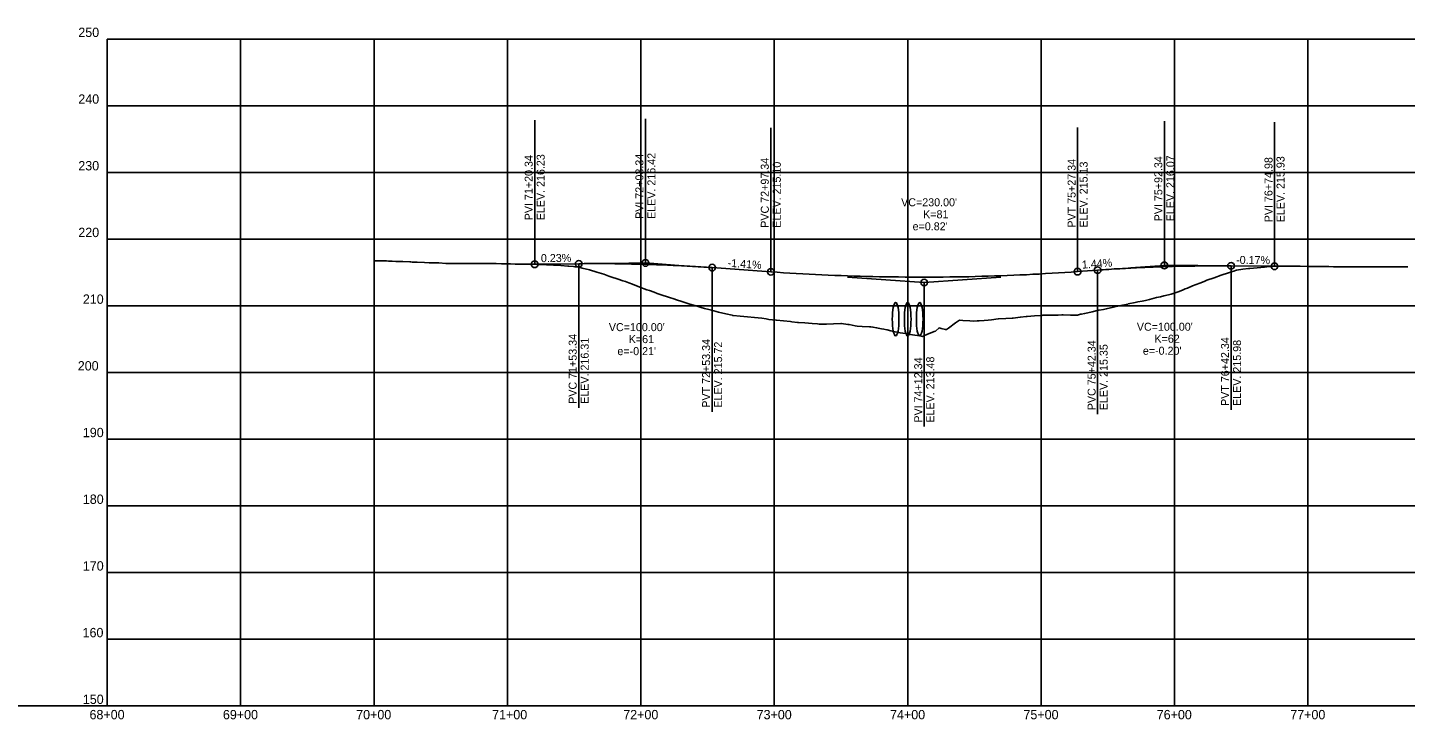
# Model space of a CAD drawing. Extents: x 1138442 to 1165793, y 1654070 to 1657687.
# Drawn here: x 1163494 to 1164527, y 1654070 to 1654589 of the extents above; entities that cross this region are included whole.
import ezdxf

# ---------------------------------------------------------------- set-up
doc = ezdxf.new("R2010")
doc.units = 0
for name, color, linetype in [('B_Dimensions', 7, 'Continuous'), ('R_Axis', 7, 'Continuous'), ('R_Axis Annot', 7, 'Continuous'), ('R_Concrete', 7, 'Continuous'), ('R_Grid', 7, 'Continuous'), ('R_No Plot', 7, 'Continuous'), ('R_Proposed Const Limits_Hand', 7, 'Continuous'), ('R_Vert Alg Annot', 7, 'Continuous')]:
    doc.layers.add(name, color=color, linetype=linetype)

msp = doc.modelspace()

# ---------------------------------------------------------------- linework, layer by layer
at = {"layer": 'B_Dimensions'}
for p, q in [((1163874, 1654411.5), (1163907, 1654411.9)), ((1163932, 1654412.2), (1163957, 1654412.5)), ((1163957, 1654412.5), (1163982, 1654410.7)), ((1164007, 1654409), (1164051, 1654405.9)), ((1164281, 1654406), (1164296, 1654407.1)), ((1164321, 1654408.9), (1164346, 1654410.7)), ((1164346, 1654410.7), (1164371, 1654410.5)), ((1164396, 1654410.3), (1164428.6, 1654410)), ((1164108.5, 1654401.8), (1164166, 1654397.8)), ((1164166, 1654397.8), (1164223.5, 1654401.9))]:
    msp.add_line(p, q, dxfattribs=at)
for points in [[(1163907, 1654411.9), (1163909.1, 1654411.9), (1163911.1, 1654412), (1163913.2, 1654412), (1163915.3, 1654412), (1163917.4, 1654412), (1163919.5, 1654412), (1163921.6, 1654412), (1163923.6, 1654412), (1163925.7, 1654412), (1163927.8, 1654412), (1163929.9, 1654412), (1163932, 1654412), (1163934.1, 1654411.9), (1163936.1, 1654411.9), (1163938.2, 1654411.9), (1163940.3, 1654411.9), (1163942.4, 1654411.8), (1163944.5, 1654411.8), (1163946.6, 1654411.7), (1163948.6, 1654411.7), (1163950.7, 1654411.6), (1163952.8, 1654411.6), (1163954.9, 1654411.5), (1163959.1, 1654411.4), (1163961.1, 1654411.3), (1163963.2, 1654411.3), (1163965.3, 1654411.2), (1163967.4, 1654411.1), (1163969.5, 1654411), (1163971.6, 1654411), (1163973.6, 1654410.9), (1163975.7, 1654410.8), (1163977.8, 1654410.7), (1163979.9, 1654410.6), (1163982, 1654410.5), (1163984.1, 1654410.4), (1163986.1, 1654410.3), (1163988.2, 1654410.2), (1163990.3, 1654410), (1163992.4, 1654409.9), (1163994.5, 1654409.8), (1163996.6, 1654409.7), (1163998.6, 1654409.5), (1164000.7, 1654409.4), (1164002.8, 1654409.3), (1164004.9, 1654409.1), (1164007, 1654409)], [(1164051, 1654405.9), (1164055.8, 1654405.5), (1164060.6, 1654405.2), (1164065.3, 1654404.9), (1164070.1, 1654404.6), (1164074.9, 1654404.4), (1164079.7, 1654404.1), (1164084.5, 1654403.9), (1164089.3, 1654403.6), (1164094.1, 1654403.4), (1164098.9, 1654403.2), (1164103.7, 1654403), (1164108.5, 1654402.8), (1164113.3, 1654402.7), (1164118.1, 1654402.5), (1164122.8, 1654402.4), (1164127.6, 1654402.3), (1164132.4, 1654402.2), (1164137.2, 1654402.1), (1164142, 1654402), (1164146.8, 1654402), (1164151.6, 1654401.9), (1164156.4, 1654401.9), (1164161.2, 1654401.9), (1164170.8, 1654401.9), (1164175.6, 1654401.9), (1164180.3, 1654401.9), (1164185.1, 1654402), (1164189.9, 1654402.1), (1164194.7, 1654402.1), (1164199.5, 1654402.2), (1164204.3, 1654402.3), (1164209.1, 1654402.5), (1164213.9, 1654402.6), (1164218.7, 1654402.8), (1164223.5, 1654402.9), (1164228.3, 1654403.1), (1164233.1, 1654403.3), (1164237.8, 1654403.5), (1164242.6, 1654403.7), (1164247.4, 1654404), (1164252.2, 1654404.2), (1164257, 1654404.5), (1164261.8, 1654404.8), (1164266.6, 1654405.1), (1164271.4, 1654405.4), (1164276.2, 1654405.7), (1164281, 1654406)], [(1164296, 1654407.1), (1164298.1, 1654407.3), (1164300.1, 1654407.4), (1164302.2, 1654407.6), (1164304.3, 1654407.7), (1164306.4, 1654407.8), (1164308.5, 1654408), (1164310.6, 1654408.1), (1164312.6, 1654408.2), (1164314.7, 1654408.3), (1164316.8, 1654408.4), (1164318.9, 1654408.6), (1164321, 1654408.7), (1164323.1, 1654408.8), (1164325.1, 1654408.9), (1164327.2, 1654409), (1164329.3, 1654409.1), (1164331.4, 1654409.2), (1164333.5, 1654409.3), (1164335.6, 1654409.3), (1164337.6, 1654409.4), (1164339.7, 1654409.5), (1164341.8, 1654409.6), (1164343.9, 1654409.7), (1164348.1, 1654409.8), (1164350.1, 1654409.8), (1164352.2, 1654409.9), (1164354.3, 1654410), (1164356.4, 1654410), (1164358.5, 1654410.1), (1164360.6, 1654410.1), (1164362.6, 1654410.1), (1164364.7, 1654410.2), (1164366.8, 1654410.2), (1164368.9, 1654410.2), (1164371, 1654410.3), (1164373.1, 1654410.3), (1164375.1, 1654410.3), (1164377.2, 1654410.3), (1164379.3, 1654410.3), (1164381.4, 1654410.3), (1164383.5, 1654410.3), (1164385.6, 1654410.3), (1164387.6, 1654410.3), (1164389.7, 1654410.3), (1164391.8, 1654410.3), (1164393.9, 1654410.3), (1164396, 1654410.3)]]:
    msp.add_lwpolyline(points, dxfattribs=at)
at = {"layer": 'R_Axis'}
for q in [(1163553.6, 1654580.4), (1165053.6, 1654080.4)]:
    msp.add_line((1163553.6, 1654080.4), q, dxfattribs=at)
at = {"layer": 'R_Concrete'}
for centre in [(1164144.6, 1654370.3), (1164153.6, 1654370.3), (1164162.6, 1654370.3)]:
    msp.add_ellipse(centre, major_axis=(0, -12.5), ratio=0.2, dxfattribs=at)
at = {"layer": 'R_Grid'}
for p, q in [((1163553.6, 1654580.4), (1165053.6, 1654580.4)), ((1163553.6, 1654580.4), (1165053.6, 1654580.4)), ((1163653.6, 1654080.4), (1163653.6, 1654580.4)), ((1163753.6, 1654080.4), (1163753.6, 1654580.4)), ((1163853.6, 1654080.4), (1163853.6, 1654580.4)), ((1163953.6, 1654080.4), (1163953.6, 1654580.4)), ((1164053.6, 1654080.4), (1164053.6, 1654580.4)), ((1164153.6, 1654080.4), (1164153.6, 1654580.4)), ((1164253.6, 1654080.4), (1164253.6, 1654580.4)), ((1164353.6, 1654080.4), (1164353.6, 1654580.4)), ((1164453.6, 1654080.4), (1164453.6, 1654580.4)), ((1163553.6, 1654530.4), (1165053.6, 1654530.4)), ((1163553.6, 1654480.4), (1165053.6, 1654480.4)), ((1163553.6, 1654430.4), (1165053.6, 1654430.4)), ((1163553.6, 1654380.4), (1165053.6, 1654380.4)), ((1163553.6, 1654330.4), (1165053.6, 1654330.4)), ((1163553.6, 1654280.4), (1165053.6, 1654280.4)), ((1163553.6, 1654230.4), (1165053.6, 1654230.4)), ((1163553.6, 1654180.4), (1165053.6, 1654180.4)), ((1163553.6, 1654130.4), (1165053.6, 1654130.4))]:
    msp.add_line(p, q, dxfattribs=at)
at = {"layer": 'R_No Plot'}
msp.add_line((1163553.6, 1654080.4), (1161984.5, 1654080.4), dxfattribs=at)
at = {"layer": 'R_Proposed Const Limits_Hand'}
msp.add_lwpolyline([(1163753.6, 1654414.2), (1163759, 1654414.1), (1163762.9, 1654414), (1163764.4, 1654413.9), (1163767, 1654413.8), (1163767.2, 1654413.8), (1163769.8, 1654413.7), (1163775.2, 1654413.5), (1163780.3, 1654413.3), (1163780.5, 1654413.3), (1163781.1, 1654413.3), (1163782.1, 1654413.2), (1163785.9, 1654413.1), (1163791.3, 1654412.9), (1163795, 1654412.7), (1163796.7, 1654412.7), (1163797.2, 1654412.7), (1163802.1, 1654412.5), (1163807.4, 1654412.2), (1163808.8, 1654412.2), (1163812.6, 1654412.2), (1163812.8, 1654412.2), (1163818.2, 1654412.2), (1163822.2, 1654412.2), (1163823.6, 1654412.1), (1163827.6, 1654412.1), (1163829, 1654412.1), (1163834.4, 1654412.1), (1163835.6, 1654412.1), (1163839.7, 1654412), (1163843.1, 1654412), (1163845.1, 1654412), (1163849.1, 1654411.9), (1163850.5, 1654411.9), (1163855.9, 1654411.8), (1163859.4, 1654411.7), (1163861.3, 1654411.7), (1163862.7, 1654411.7), (1163866.6, 1654411.6), (1163872, 1654411.6), (1163875, 1654411.5), (1163876, 1654411.5), (1163876.7, 1654411.4), (1163877.4, 1654411.4), (1163882.8, 1654411.1), (1163888.2, 1654410.8), (1163888.2, 1654410.8), (1163893.5, 1654410.5), (1163898.9, 1654410.1), (1163899.6, 1654410), (1163903, 1654409.8), (1163904.2, 1654409.7), (1163904.3, 1654409.7), (1163906.7, 1654409.5), (1163909.7, 1654408.7), (1163915.1, 1654407.3), (1163920.5, 1654405.7), (1163920.5, 1654405.7), (1163925.8, 1654404), (1163929.5, 1654402.7), (1163931.2, 1654402.2), (1163936.6, 1654400.4), (1163940.2, 1654399.2), (1163942, 1654398.6), (1163944.6, 1654397.7), (1163947.4, 1654396.6), (1163952.7, 1654394.4), (1163952.7, 1654394.4), (1163958.1, 1654392.4), (1163960, 1654391.8), (1163963.5, 1654390.5), (1163965.8, 1654389.7), (1163968.9, 1654388.6), (1163974.3, 1654386.8), (1163979.1, 1654385.3), (1163979.6, 1654385.1), (1163985, 1654383.4), (1163985.9, 1654383.2), (1163990.4, 1654381.7), (1163995.8, 1654380), (1163998.7, 1654379.1), (1164001.2, 1654378.4), (1164004.5, 1654377.6), (1164006.6, 1654377), (1164011.9, 1654375.7), (1164017.3, 1654374.4), (1164022.1, 1654373.3), (1164022.2, 1654373.2), (1164022.7, 1654373.1), (1164022.7, 1654373.1), (1164028.1, 1654372.6), (1164033.5, 1654372.2), (1164038.7, 1654371.7), (1164038.8, 1654371.7), (1164044.2, 1654371), (1164047.6, 1654370.5), (1164049.6, 1654370.2), (1164055, 1654369.5), (1164055.3, 1654369.5), (1164060.4, 1654369), (1164065.8, 1654368.5), (1164066.7, 1654368.4), (1164071.1, 1654367.9), (1164071.7, 1654367.9), (1164076.5, 1654367.5), (1164081.9, 1654367.1), (1164086, 1654366.8), (1164087.3, 1654366.7), (1164088.9, 1654366.5), (1164092.7, 1654366.6), (1164098, 1654366.8), (1164103.4, 1654367), (1164104.1, 1654367), (1164108.8, 1654366.4), (1164109.8, 1654366.3), (1164114.2, 1654365.4), (1164115.8, 1654365.1), (1164119.6, 1654364.9), (1164124.9, 1654364.7), (1164126, 1654364.6), (1164127.5, 1654364.4), (1164127.5, 1654364.4), (1164130.3, 1654363.9), (1164134, 1654363.2), (1164135.7, 1654362.9), (1164138.1, 1654362.4), (1164138.3, 1654362.4), (1164141.1, 1654361.7), (1164146.5, 1654360.5), (1164148.1, 1654360.1), (1164151.9, 1654359.6), (1164154.2, 1654359.2), (1164157.2, 1654358.7), (1164162.6, 1654357.8), (1164164.7, 1654357.4), (1164166.3, 1654358.1), (1164168, 1654358.8), (1164173.4, 1654361.1), (1164174.4, 1654361.5), (1164177.2, 1654363.9), (1164178.8, 1654363.4), (1164181.9, 1654362.6), (1164182.8, 1654362.6), (1164184.1, 1654363.6), (1164189.5, 1654367.5), (1164192.4, 1654369.6), (1164194.9, 1654369.4), (1164200.3, 1654369.1), (1164203.1, 1654368.9), (1164205.7, 1654369), (1164207.3, 1654369.1), (1164211, 1654369.3), (1164213.9, 1654369.5), (1164216.4, 1654369.8), (1164221.4, 1654370.5), (1164221.8, 1654370.6), (1164227.2, 1654370.8), (1164231.9, 1654371.1), (1164232.6, 1654371.2), (1164238, 1654371.8), (1164238.1, 1654371.8), (1164242.5, 1654372.4), (1164243.3, 1654372.4), (1164248.7, 1654372.8), (1164254.1, 1654373.2), (1164254.9, 1654373.3), (1164259.5, 1654373.3), (1164264.9, 1654373.3), (1164266.4, 1654373.3), (1164269.2, 1654373.5), (1164270.2, 1654373.5), (1164275.6, 1654373.4), (1164280.5, 1654373.3), (1164281, 1654373.4), (1164283.1, 1654374), (1164283.7, 1654374), (1164286.4, 1654374.7), (1164291.8, 1654375.9), (1164296.6, 1654377.1), (1164297.2, 1654377.2), (1164300.3, 1654377.6), (1164302.5, 1654378.1), (1164307.9, 1654379.4), (1164310, 1654379.9), (1164313.3, 1654380.6), (1164318.7, 1654381.7), (1164318.9, 1654381.8), (1164324.1, 1654382.8), (1164326.2, 1654383.3), (1164329.4, 1654383.9), (1164331.8, 1654384.4), (1164334.8, 1654385.2), (1164340.2, 1654386.5), (1164343.1, 1654387.2), (1164345.6, 1654387.8), (1164345.8, 1654387.9), (1164351, 1654389.2), (1164355.7, 1654390.5), (1164356.3, 1654390.8), (1164359.5, 1654392.2), (1164361.7, 1654393.1), (1164363.3, 1654393.7), (1164367.1, 1654395.3), (1164372.5, 1654397.4), (1164375.8, 1654398.7), (1164377.9, 1654399.5), (1164383.3, 1654401.4), (1164388.6, 1654403.3), (1164394, 1654405.1), (1164395.7, 1654405.7), (1164397.2, 1654406.2), (1164398, 1654406.4), (1164399.4, 1654406.9), (1164400.1, 1654407.2), (1164404.8, 1654407.8), (1164409, 1654408.3), (1164410.2, 1654408.4), (1164415.5, 1654408.9), (1164418.4, 1654409.1), (1164419.8, 1654409.3), (1164420.9, 1654409.4), (1164421.2, 1654409.4), (1164422.9, 1654409.5), (1164426.3, 1654409.8), (1164428.6, 1654410), (1164431.7, 1654410), (1164437.1, 1654410), (1164439.2, 1654410), (1164442.5, 1654410), (1164447.8, 1654410), (1164453.2, 1654409.9), (1164454.2, 1654409.9), (1164458.6, 1654409.9), (1164463.1, 1654409.8), (1164464, 1654409.8), (1164469.4, 1654409.8), (1164472.7, 1654409.7), (1164474.7, 1654409.7), (1164480.1, 1654409.7), (1164485.5, 1654409.6), (1164486.9, 1654409.6), (1164490.9, 1654409.6), (1164491.3, 1654409.6), (1164496.3, 1654409.6), (1164501.6, 1654409.6), (1164506.3, 1654409.6), (1164507, 1654409.6), (1164512.4, 1654409.6), (1164517.8, 1654409.6), (1164522.8, 1654409.6), (1164523.2, 1654409.6), (1164525.4, 1654409.6), (1164525.6, 1654409.5), (1164528.6, 1654409.5)], dxfattribs=at)
at = {"layer": 'R_Vert Alg Annot'}
for p, q in [((1163957, 1654442.5), (1163957, 1654520.5)), ((1163874, 1654441.5), (1163874, 1654519.5)), ((1164051, 1654435.9), (1164051, 1654513.9)), ((1164281, 1654436), (1164281, 1654514)), ((1164346, 1654440.7), (1164346, 1654518.7)), ((1164428.6, 1654440), (1164428.6, 1654518)), ((1163874, 1654411.5), (1163874, 1654441.5)), ((1163957, 1654412.5), (1163957, 1654442.5)), ((1164346, 1654410.7), (1164346, 1654440.7)), ((1164428.6, 1654410), (1164428.6, 1654440)), ((1164051, 1654405.9), (1164051, 1654435.9)), ((1164281, 1654406), (1164281, 1654436)), ((1163907, 1654411.9), (1163907, 1654381.9)), ((1164007, 1654409), (1164007, 1654379)), ((1164296, 1654407.1), (1164296, 1654377.1)), ((1164396, 1654410.3), (1164396, 1654380.3)), ((1164166, 1654397.8), (1164166, 1654367.8)), ((1163907, 1654381.9), (1163907, 1654303.9)), ((1164007, 1654379), (1164007, 1654301)), ((1164296, 1654377.1), (1164296, 1654299.1)), ((1164396, 1654380.3), (1164396, 1654302.3)), ((1164166, 1654367.8), (1164166, 1654289.8))]:
    msp.add_line(p, q, dxfattribs=at)
for centre in [(1163874, 1654411.5), (1163907, 1654411.9), (1163957, 1654412.5), (1164007, 1654409), (1164051, 1654405.9), (1164281, 1654406), (1164296, 1654407.1), (1164346, 1654410.7), (1164396, 1654410.3), (1164428.6, 1654410), (1164166, 1654397.8)]:
    msp.add_circle(centre, 2.5, dxfattribs=at)

# ---------------------------------------------------------------- texts
at = {"layer": 'R_Axis Annot'}
for s, height, p in [('250', 7, (1163531.9, 1654581.9)), ('250', 7, (1163531.9, 1654581.9)), ('240', 7, (1163531.9, 1654531.9)), ('230', 7, (1163531.9, 1654481.9)), ('220', 7, (1163531.9, 1654431.9)), ('210', 7, (1163535.3, 1654381.9)), ('200', 7, (1163531.5, 1654331.9)), ('190', 7, (1163535.3, 1654281.9)), ('180', 7, (1163535.3, 1654231.9)), ('170', 7, (1163535.3, 1654181.9)), ('160', 7, (1163535.1, 1654131.9)), ('150', 7, (1163535.3, 1654081.9)), ('68+00', 7, (1163540.3, 1654070.4)), ('-', 0.0001, (1163553.6, 1654080.4)), ('69+00', 7, (1163640.3, 1654070.4)), ('70+00', 7, (1163740.2, 1654070.4)), ('71+00', 7, (1163842.1, 1654070.4)), ('72+00', 7, (1163940.4, 1654070.4)), ('73+00', 7, (1164040.4, 1654070.4)), ('74+00', 7, (1164140.4, 1654070.4)), ('75+00', 7, (1164240.4, 1654070.4)), ('76+00', 7, (1164340.3, 1654070.4)), ('77+00', 7, (1164440.4, 1654070.4))]:
    msp.add_text(s, height=height, dxfattribs=at).set_placement(p)
at = {"layer": 'R_Vert Alg Annot'}
for s, rotation, p in [('PVI 71+20.34', 90, (1163872.5, 1654444.5)), ('ELEV. 216.23', 90, (1163881.5, 1654444.5)), ('PVI 72+03.34', 90, (1163955.5, 1654445.5)), ('ELEV. 216.42', 90, (1163964.5, 1654445.5)), ('PVC 72+97.34', 90, (1164049.5, 1654438.9)), ('PVT 75+27.34', 90, (1164279.5, 1654439)), ('PVI 75+92.34', 90, (1164344.5, 1654443.7)), ('ELEV. 216.07', 90, (1164353.5, 1654443.7)), ('PVI 76+74.98', 90, (1164427.1, 1654443)), ('ELEV. 215.93', 90, (1164436.1, 1654443)), ('ELEV. 215.10', 90, (1164058.5, 1654438.9)), ('ELEV. 215.13', 90, (1164288.5, 1654439)), ('0.23%', 0.6589, (1163878.7, 1654413.1)), ('-0.17%', 359.513, (1164399.8, 1654411.8)), ('-1.41%', 355.9673, (1164018.5, 1654409.7)), ('1.44%', 4.1182, (1164284.4, 1654408.2)), ('PVC 71+53.34', 90, (1163905.5, 1654306.9)), ('ELEV. 216.31', 90, (1163914.5, 1654306.9)), ('PVT 72+53.34', 90, (1164005.5, 1654304)), ('PVC 75+42.34', 90, (1164294.5, 1654302.1)), ('PVT 76+42.34', 90, (1164394.5, 1654305.3)), ('ELEV. 215.98', 90, (1164403.5, 1654305.3)), ('ELEV. 215.72', 90, (1164014.5, 1654304)), ('ELEV. 215.35', 90, (1164303.5, 1654302.1)), ('PVI 74+12.34', 90, (1164164.5, 1654292.8)), ('ELEV. 213.48', 90, (1164173.5, 1654292.8))]:
    msp.add_text(s, height=6, rotation=rotation, dxfattribs=at).set_placement(p)
for s, p in [("VC=230.00'", (1164148.7, 1654455)), ('K=81', (1164165.2, 1654446)), ("e=0.82'", (1164157.3, 1654437)), ("VC=100.00'", (1163929.6, 1654361.4)), ("VC=100.00'", (1164325.4, 1654361.7)), ('K=61', (1163944.5, 1654352.4)), ('K=62', (1164338.6, 1654352.7)), ("e=-0.21'", (1163936, 1654343.4)), ("e=-0.20'", (1164329.9, 1654343.7))]:
    msp.add_text(s, height=6, dxfattribs=at).set_placement(p)

doc.saveas('drawing.dxf')
